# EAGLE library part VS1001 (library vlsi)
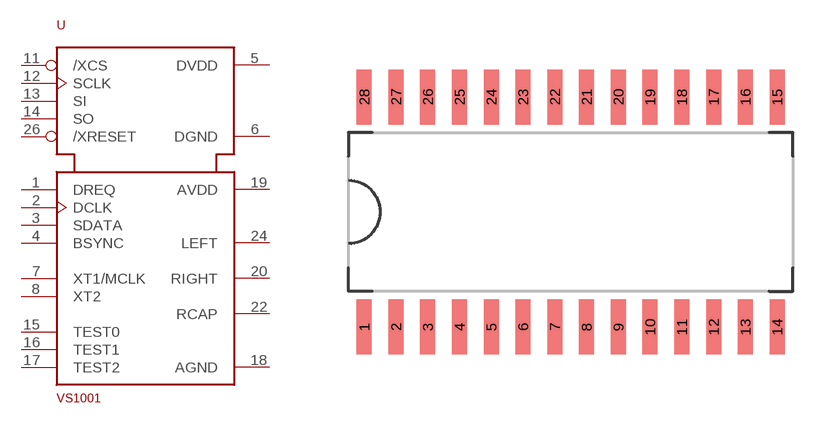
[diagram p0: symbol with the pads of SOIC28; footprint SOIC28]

Designator prefix -

## VS1001SOIC28  [SOIC28]
1  DREQ  out
2  DCLK  in
3  SDATA  in
4  BSYNC  in
5  DVDD  pwr
6  DGND  pwr
7  XT1/MCLK
8  XT2
9  DVDD  pwr
10  DGND  pwr
11  /XCS  in
12  SCLK  in
13  SI  in
14  SO  out
15  TEST0  in
16  TEST1  nc
17  TEST2  nc
18  AGND  pwr
19  AVDD  pwr
20  RIGHT  out
21  AGND  pwr
22  RCAP
23  AVDD  pwr
24  LEFT  out
25  AGND  pwr
26  /XRESET  in
27  DGND  pwr
28  DVDD  pwr

## Footprint SOIC28 (pad centres in mm)
smd 0.6 x 2.2: 1 -8.255,-4.6; 2 -6.985,-4.6; 3 -5.715,-4.6; 4 -4.445,-4.6; 5 -3.175,-4.6; 6 -1.905,-4.6; 7 -0.635,-4.6; 8 0.635,-4.6; 9 1.905,-4.6; 10 3.175,-4.6; 11 4.445,-4.6; 12 5.715,-4.6; 13 6.985,-4.6; 14 8.255,-4.6; 15 8.255,4.6; 16 6.985,4.6; 17 5.715,4.6; 18 4.445,4.6; 19 3.175,4.6; 20 1.905,4.6; 21 0.635,4.6; 22 -0.635,4.6; 23 -1.905,4.6; 24 -3.175,4.6; 25 -4.445,4.6; 26 -5.715,4.6; 27 -6.985,4.6; 28 -8.255,4.6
